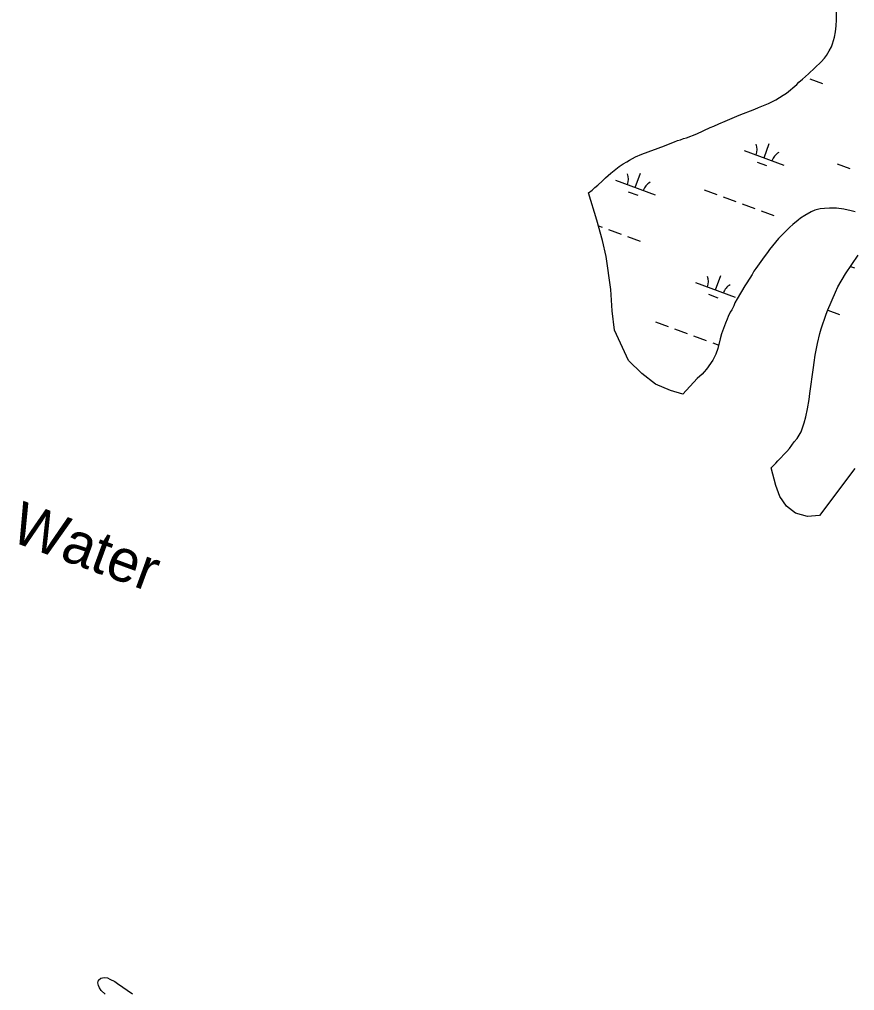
# Model space of a CAD drawing. Extents: x 3972907 to 3994831, y 172639 to 190852.
# Drawn here: x 3980180 to 3981167, y 182890 to 184038 of the extents above; entities that cross this region are included whole.
import ezdxf

# ---------------------------------------------------------------- set-up
doc = ezdxf.new("R2010")
doc.units = 0
doc.layers.add('V-RIVR-IDEN', color=7, linetype='Continuous')
doc.layers.add('V-WETL-SWMP', color=7, linetype='Continuous')

msp = doc.modelspace()

# ---------------------------------------------------------------- linework, layer by layer
at = {"layer": 'V-WETL-SWMP'}
for p, q in [((3981114, 183968), (3981129, 183962.5)), ((3981036.4, 183883.3), (3981083.3, 183866.1)), ((3981059.9, 183874.7), (3981066.1, 183891.6)), ((3981051.6, 183869.5), (3981062.8, 183865.4)), ((3981146.3, 183867.7), (3981161.3, 183862.1)), ((3980907.7, 183839.6), (3980913.9, 183856.5)), ((3980884.2, 183848.2), (3980931.2, 183831)), ((3980899.4, 183834.4), (3980910.7, 183830.3)), ((3980989, 183836.8), (3981004, 183831.2)), ((3981011.5, 183828.5), (3981026.5, 183823)), ((3981034.1, 183820.2), (3981049.1, 183814.7)), ((3981056.6, 183811.9), (3981071.6, 183806.4)), ((3980864.1, 183794.2), (3980868.4, 183792.6)), ((3980875.9, 183789.8), (3980890.9, 183784.3)), ((3980898.4, 183781.5), (3980913.4, 183776)), ((3981162.1, 183746.1), (3981166.7, 183744.4)), ((3981002.5, 183718.6), (3981008.7, 183735.5)), ((3980979, 183727.2), (3981025.9, 183709.9)), ((3980994.2, 183713.4), (3981005.4, 183709.2)), ((3981135.3, 183694.5), (3981149, 183689.4)), ((3980931.6, 183680.6), (3980946.6, 183675.1)), ((3980954.1, 183672.4), (3980969.2, 183666.8)), ((3980976.7, 183664.1), (3980991.7, 183658.6)), ((3980999.2, 183655.8), (3981006.3, 183653.2))]:
    msp.add_line(p, q, dxfattribs=at)
for points in [[(3980986.6, 183618.8), (3980980.8, 183613.8), (3980963.9, 183595.1), (3980949.3, 183599.6), (3980931.5, 183607), (3980915.4, 183619.5), (3980899.7, 183634.9), (3980883.1, 183670.7), (3980880.4, 183693.8), (3980878.7, 183719.1), (3980873.4, 183757.8), (3980868.9, 183776.9), (3980862.1, 183801.1), (3980852.6, 183833.1), (3980856.8, 183836.5), (3980860, 183839.6), (3980863.6, 183842.4), (3980869.1, 183847.3), (3980872.7, 183851.1), (3980878.8, 183856.6), (3980888.6, 183864.2), (3980893.3, 183867.4), (3980897.7, 183870), (3980900.7, 183871.9), (3980908.1, 183875.9), (3980915.5, 183879.1), (3980942.2, 183888.8), (3980950.9, 183892.4), (3980954.1, 183893.5), (3980957.7, 183895), (3980961.3, 183896), (3980964.7, 183897.3), (3980968.1, 183898.4), (3980980.6, 183903), (3980996.2, 183910.5), (3981000.5, 183912.2), (3981006.6, 183914.9), (3981014, 183917.9), (3981030.6, 183924.9), (3981049, 183932.3), (3981053.2, 183934.2), (3981065.3, 183938.9), (3981074, 183943.3), (3981082.7, 183948.6), (3981086.3, 183951.2), (3981098.6, 183961.4), (3981101.1, 183963.9), (3981105.4, 183967.5), (3981112.6, 183974.1), (3981127.6, 183988.1), (3981131.2, 183992.5), (3981133.6, 183995.7), (3981136.9, 184001.2), (3981139.5, 184005.9), (3981140.8, 184009.5), (3981143.1, 184017.1), (3981144.4, 184023.5), (3981145.2, 184030.7), (3981145.6, 184037.9), (3981145.6, 184053.1)], [(3981167.7, 183810.7), (3981163.1, 183812), (3981154.4, 183813.9), (3981145.5, 183815.1), (3981141.4, 183815.3), (3981137.4, 183815.3), (3981131.5, 183814.9), (3981126.2, 183814.3), (3981120, 183812.6), (3981115.8, 183810.9), (3981108, 183806.6), (3981103.1, 183803.3), (3981100.3, 183801.1), (3981094, 183796), (3981090.4, 183792.7), (3981080.2, 183782.5), (3981077.2, 183779.3), (3981066.4, 183766.4), (3981063.9, 183762.8), (3981059.9, 183757.7), (3981050.1, 183743.7), (3981048, 183740.5), (3981045.7, 183736.5), (3981039.7, 183726.9), (3981037.2, 183723.1), (3981028.1, 183707.9), (3981025.5, 183703.2), (3981024.1, 183699.8), (3981021.7, 183695.1), (3981019.8, 183692), (3981017.7, 183686.9), (3981016.2, 183683.9), (3981014.3, 183679.3), (3981009.7, 183666.7), (3981008, 183660.8), (3981005.4, 183649.4), (3981002.9, 183642.4), (3980999.5, 183635.6), (3980991.9, 183624.8), (3980989.1, 183621.6), (3980986.6, 183618.8)], [(3981167.2, 183507.2), (3981125.4, 183451.9), (3981111.2, 183450.6), (3981097.2, 183454.4), (3981086.4, 183462.7), (3981078.4, 183474.3), (3981073.9, 183487.3), (3981068.2, 183508.2), (3981073.7, 183513.5), (3981076.2, 183516.5), (3981087, 183527.5), (3981090.2, 183531.1), (3981095.7, 183538.8), (3981099.1, 183543), (3981103.8, 183550.6), (3981107.4, 183561.2), (3981109.3, 183568.4), (3981111.2, 183578), (3981113.1, 183588.8), (3981114.2, 183596), (3981118.2, 183626.9), (3981119.2, 183632.7), (3981120.3, 183641.3), (3981123, 183655.3), (3981125.8, 183666.8), (3981127.3, 183672.3), (3981133.4, 183689.7), (3981135.5, 183695), (3981144.2, 183715.7), (3981147.2, 183722.1), (3981156.1, 183737.4), (3981171.3, 183759.6)], [(3980281.2, 182885.7), (3980276.3, 182890.3), (3980274.3, 182893.2), (3980273.1, 182896.1), (3980272.5, 182899.4), (3980273.2, 182902.3), (3980276.1, 182904.9), (3980279.8, 182905.6), (3980283.8, 182905), (3980286.7, 182903.8), (3980292.5, 182900.9), (3980295.8, 182898.6), (3980313.4, 182886.1)]]:
    msp.add_lwpolyline(points, dxfattribs=at)
for centre, start, end in [((3981034, 183884.4), 339.0473, 20.5909), ((3981085.9, 183865.4), 119.0473, 160.5909), ((3980881.9, 183849.4), 339.0473, 20.5909), ((3980933.7, 183830.3), 119.0473, 160.5909), ((3980976.6, 183728.3), 339.0473, 20.5909), ((3981028.5, 183709.2), 119.0473, 160.5909)]:
    msp.add_arc(centre, 17.6, start, end, dxfattribs=at)

# ---------------------------------------------------------------- texts
at = {"layer": 'V-RIVR-IDEN'}
msp.add_text('Water', height=50, rotation=339.8191, dxfattribs=at).set_placement((3980166.7, 183422.4))

doc.saveas('drawing.dxf')
